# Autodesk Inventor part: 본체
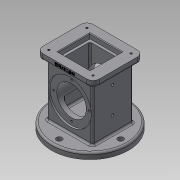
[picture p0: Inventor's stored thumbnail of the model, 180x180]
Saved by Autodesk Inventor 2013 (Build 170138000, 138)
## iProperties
Created: 2018-10
Part Number: 본체
Material: 일반
Document SubType Name: Modeling
Designer: hana-cad36
Density: 1 g/cm^3
Author: hana-cad36
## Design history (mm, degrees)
sketch "스케치1"
  geometry: C1 r 62.5 at (0, 0); 1 further point
  constraints: 1 centre point, 1 coincident
  dimensions: "d0" = 62.5 radius of C1
extrude "돌출1" new body sketch "스케치1" distance "d1" = 10; taper "d2" = 0 deg
node "작업 평면1"
sketch "스케치3"
  geometry: L1 (46, -41)-(-46, -41); L2 (-46, -41)-(-46, 41); L3 (-46, 41)-(46, 41); L4 (46, 41)-(46, -41); L5 (46, -41)-(-46, 41); L6 (-46, -41)-(46, 41); 1 further point
  constraints: 12 end point, 2 midpoint, 2 parallel, 1 horizontal, 1 perpendicular
  dimensions: "d8" = 92 distance of L2.end L3.end; "d10" = 82 distance of L3.end L1.start
extrude "돌출2" join sketch "스케치3" distance "d11" = 10; taper "d12" = 0 deg
sketch "스케치4"
  geometry: L1 (37, -33)-(-37, -33); L2 (-37, -33)-(-37, 33); L3 (-37, 33)-(37, 33); L4 (37, 33)-(37, -33); L5 (37, -33)-(-37, 33); L6 (-37, -33)-(37, 33); C1 r 62.5 at (0, 0) reference
  constraints: 12 end point, 2 midpoint, 2 parallel, 1 horizontal, 1 perpendicular
  dimensions: "d13" = 74 distance of L2.end L3.end; "d15" = 66 distance of L3.end L1.start
extrude "돌출3" join sketch "스케치4" stored distance "d16" = 10; taper "d17" = 0 deg
node "작업 평면2"
node "작업 평면3"
sketch "스케치7"
  geometry: L1 (62.5, 10)-(62.5, 0) reference; L2 (62.5, 0)-(-62.5, 0) reference; L3 (-62.5, 0)-(-62.5, 10) reference; L4 (-62.5, 10)-(-33, 10) reference; L5 (-33, 10)-(-33, 98) reference; L6 (-33, 98)-(-41, 98) reference; L7 (-41, 98)-(-41, 108) reference; L8 (-41, 108)-(41, 108) reference; L9 (41, 108)-(41, 98) reference; L10 (41, 98)-(33, 98) reference; L11 (33, 98)-(33, 10) reference; L12 (33, 10)-(62.5, 10) reference; L13 (-33, 54)-(33, 54); L14 (-33, 89)-(-30, 89); L15 (-30, 89)-(-30, 78); L16 (-30, 78)-(30, 78); L17 (30, 78)-(30, 89); L18 (30, 89)-(33, 89); 3 further points
  constraints: 12 end point, 4 midpoint, 3 parallel, 2 perpendicular, 2 point on line, 1 collinear, 1 vertical alignment
  dimensions: "d32" = 70 diameter of L18 L13; "d34" = 3 distance of L17.end L18.end; "d35" = 48 diameter of L16 L13
revolve "회전1" sketch "스케치7" stored, may be unused: angle "d36" = 90 deg
sketch "스케치8"
  geometry: L1 (26, -26)-(-26, -26); L2 (-26, -26)-(-26, 26); L3 (-26, 26)-(26, 26); L4 (26, 26)-(26, -26); L5 (26, -26)-(-26, 26); L6 (-26, -26)-(26, 26); 1 further point
  constraints: 12 end point, 2 midpoint, 2 parallel, 2 perpendicular, 1 horizontal
  dimensions: "d37" = 52 distance of L2.end L3.end
extrude "돌출4" cut sketch "스케치8" distance "d39" = 8; taper "d40" = 0 deg
sketch "스케치9"
  geometry: L1 (22, -22)-(-22, -22); L2 (-22, -22)-(-22, 22); L3 (-22, 22)-(22, 22); L4 (22, 22)-(22, -22); L5 (22, -22)-(-22, 22); L6 (-22, -22)-(22, 22); 1 further point
  constraints: 12 end point, 2 midpoint, 2 parallel, 2 perpendicular, 1 horizontal
  dimensions: "d41" = 44 distance of L2.end L3.end
extrude "돌출5" cut sketch "스케치9" distance "d43" = 74; taper "d44" = 0 deg
sketch "스케치10"
  geometry: C1 r 62.5 at (0, 0) reference; 1 further point
  constraints: 1 vertical alignment
  dimensions: "d45" = 50 distance of point (0, 50) C1.centre
hole "구멍1" sketch "스케치10" at (0, 50) diameter "d46" = 9; stored, may be unused: countersink angle "d50" = 90 deg, drill point angle "d52" = 118 deg; dims "d47" = 6, "d48" = 4, "d49" = 2, "d51" = 8
sketch "스케치11"
  geometry: C1 r 35 at (0, 0) reference; 2 further points
  constraints: 1 vertical alignment
  dimensions: "d56" = 29 distance of point (0, 29) C1.centre
hole "구멍2" sketch "스케치11" at (0, 29) diameter "d57" = 3.242; stored, may be unused: countersink angle "d61" = 90 deg, drill point angle "d63" = 118 deg; dims "d58" = 4, "d59" = 4, "d60" = 2, "d62" = 6
sketch "스케치12"
  geometry: L1 (0, 66)-(0, 0) reference; L2 (10, -29.5)-(10, 95.5) reference; 4 further points
  constraints: 2 horizontal alignment, 1 midpoint
  dimensions: "d67" = 37 distance from line of point (-27, 33) L2; "d68" = 43 distance of point (-70, 33) point (-27, 33)
hole "구멍3" sketch "스케치12" at (-70, 33), (-27, 33) diameter "d69" = 4.134; stored, may be unused: countersink angle "d73" = 90 deg, drill point angle "d75" = 118 deg; dims "d70" = 43 (= d68), "d71" = 4, "d72" = 2, "d74" = 43 (= d68)
node "작업 평면4"
sketch "스케치14"
  geometry: L1 (37, 39.067)-(22, 39.067) reference; L2 (22, 63.592)-(22, 77.933) reference; L3 (22, 77.933)-(37, 77.933) reference; L4 (37, 77.933)-(37, 39.067) reference; L5 (26, 100)-(26, 108) reference; L6 (26, 108)-(46, 108) reference; L7 (46, 108)-(46, 98) reference; L8 (46, 98)-(37, 98) reference; L9 (37, 98)-(37, 82.067) reference; L10 (37, 82.067)-(22, 82.067) reference; L11 (22, 82.067)-(22, 100) reference; L12 (22, 100)-(26, 100) reference; L13 (-37, 10)-(-37, 98) reference; L14 (-37, 98)-(-46, 98) reference; L15 (-46, 98)-(-46, 108) reference; L16 (-46, 108)-(-26, 108) reference; L17 (-26, 108)-(-26, 100) reference; L18 (-26, 100)-(-22, 100) reference; L19 (-22, 100)-(-22, 63.592) reference; L20 (22, 34.933)-(37, 34.933) reference; L21 (37, 34.933)-(37, 10) reference; L22 (37, 10)-(45.5, 10) reference; L23 (45.5, 10)-(45.5, 0) reference; L24 (45.5, 0)-(-45.5, 0) reference; L25 (-45.5, 0)-(-45.5, 10) reference; L26 (-45.5, 10)-(-37, 10) reference; L27 (-62.5, 0)-(-62.5, 10) reference; L28 (-62.5, 10)-(-54.5, 10) reference; L29 (-54.5, 10)-(-54.5, 0) reference; L30 (-54.5, 0)-(-62.5, 0) reference; L31 (62.5, 10)-(62.5, 0) reference; L32 (62.5, 0)-(54.5, 0) reference; L33 (54.5, 0)-(54.5, 10) reference; L34 (54.5, 10)-(62.5, 10) reference; L35 (0, 0)-(0, 18); L36 (0, 18)-(-24.826, 18); L37 (-24.826, 18)-(-28, 0); L38 (22, 39.067)-(22, 44.408) reference; L39 (-22, 44.408)-(-22, 26) reference; L40 (-22, 26)-(22, 26) reference; L41 (22, 26)-(22, 34.933) reference; A1 r 24 centre (0, 54) between (22, 44.408) and (22, 63.592) reference; A2 r 24 centre (0, 54) between (-22, 63.592) and (-22, 44.408) reference; 1 further point
  constraints: 6 end point, 2 perpendicular, 1 midpoint, 1 point on line, 1 vertical alignment
  dimensions: "d80" = 18 distance between parallel lines of L36 L24; "d81" = 80 deg angle of L37 L24; "d82" = 56 diameter of L37.end L35
revolve "회전2" sketch "스케치14" stored, may be unused: angle "d83" = 90 deg
fillet "모깎기1" dims "d84" = 10
sketch "스케치16"
  geometry: A1 r 10 centre (-36, 31) between (-36, 41) and (-46, 31) reference; A2 r 10 centre (-36, -31) between (-46, -31) and (-36, -41) reference; A3 r 10 centre (36, -31) between (36, -41) and (46, -31) reference; A4 r 10 centre (36, 31) between (46, 31) and (36, 41) reference; 1 further point
hole "구멍4" sketch "스케치16" at (-36, 31), (-36, -31), (36, -31), (36, 31) diameter "d85" = 3.242; stored, may be unused: countersink angle "d89" = 90 deg, drill point angle "d91" = 118 deg; dims "d86" = 4, "d87" = 4, "d88" = 2, "d90" = 6
sketch "스케치17"
  geometry: L1 (0, 10)-(72, 10) reference; L2 (-10, 10)-(-10, 0) reference; 2 further points
  constraints: 1 other
  dimensions: "d92" = 46 distance from line of point (36, 6) L2; "d93" = 4 distance from line of L1 point (36, 6)
feature "엠보싱1" sketch "스케치17" dims "d94" = 0.5, "d95" = 0
chamfer "모따기1" distance "d96" = 1; stored, may be unused: second distance "d97" = 2, angle "d98" = 45 deg
fillet "모깎기2" dims "d99" = 3
fillet "모깎기3" dims "d100" = 3
fillet "모깎기4" dims "d101" = 3
fillet "모깎기5" dims "d102" = 3
fillet "모깎기6" dims "d103" = 3
fillet "모깎기7" dims "d104" = 3
fillet "모깎기8" dims "d105" = 3
fillet "모깎기9" dims "d106" = 3
fillet "모깎기10" dims "d107" = 3
node "솔리드1"
pattern_circular "원형 패턴1" dims angle "d54" = 360 deg
pattern_circular "원형 패턴2" dims angle "d65" = 360 deg
mirror "대칭1"
node "절단 모서리 투영2"
node "절단 모서리 투영3"
other parameters: "d7" = 98, "d22" = 90 deg, "d31" = 0, "d77" = 90 deg
